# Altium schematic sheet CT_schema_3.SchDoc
size 339 x 183 mm
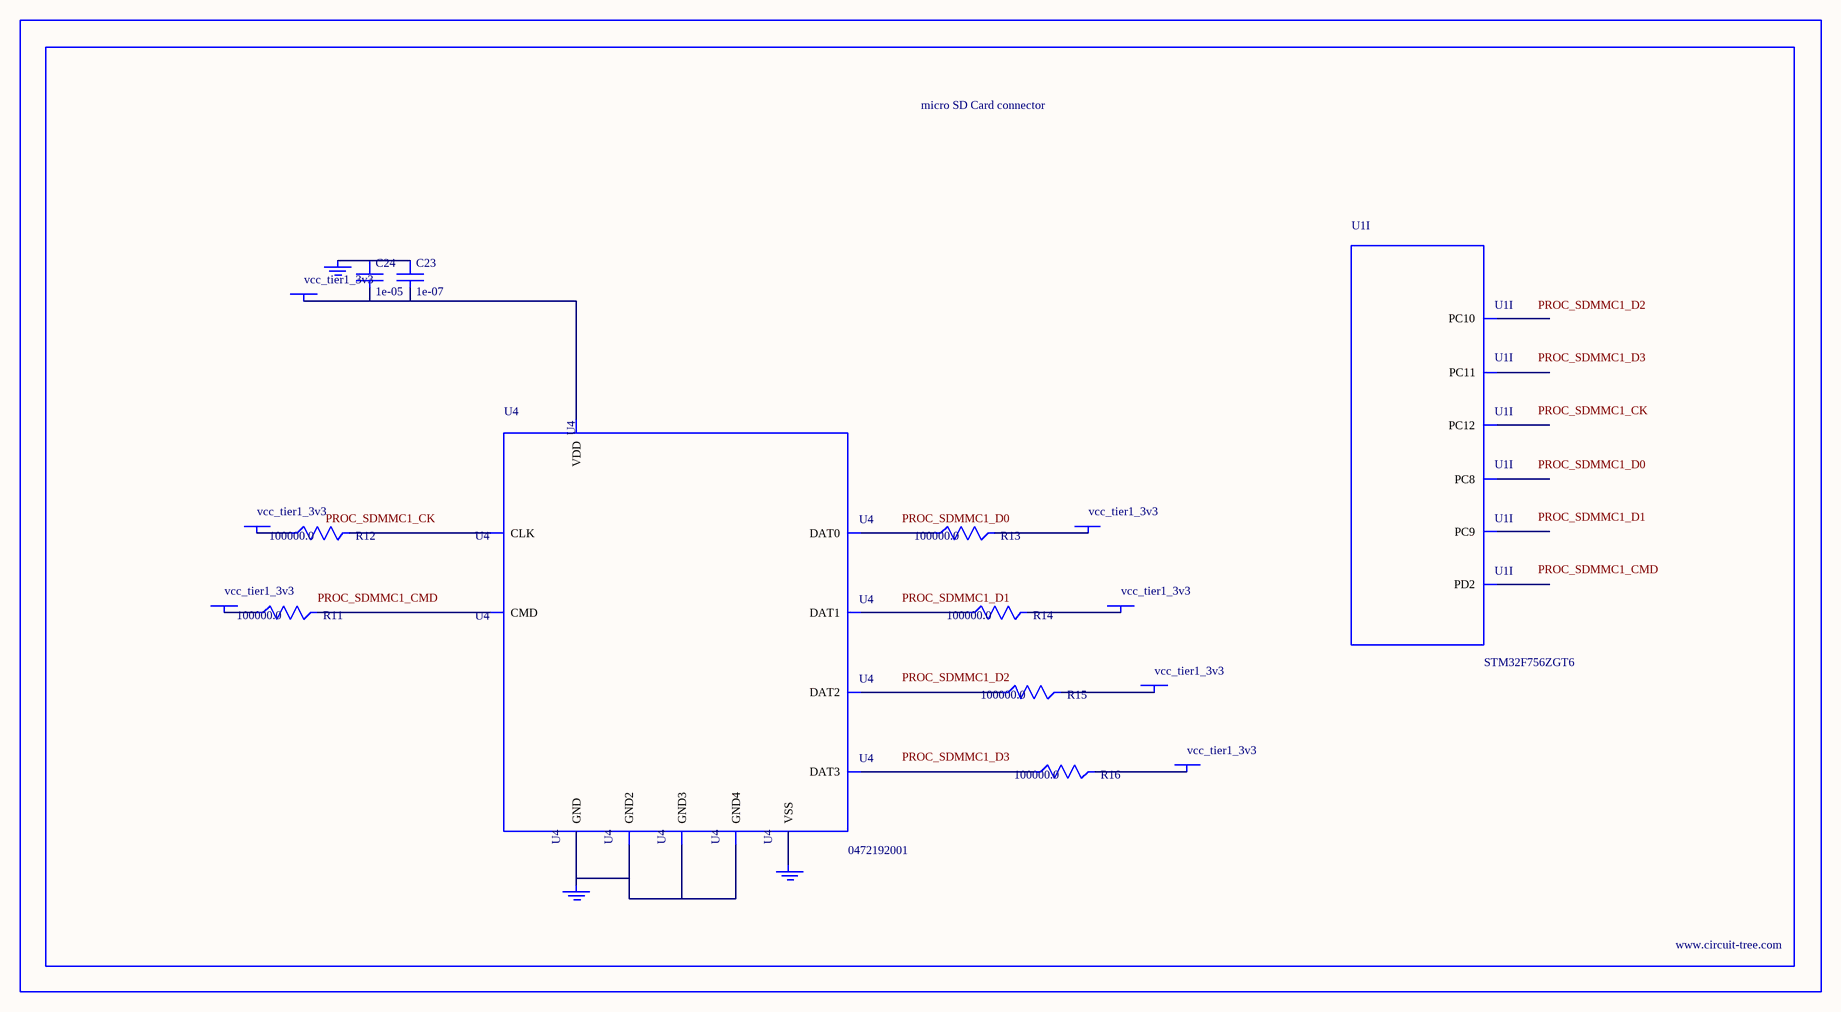
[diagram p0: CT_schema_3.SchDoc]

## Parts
BORDER2  (no value)
C23  1e-07  [C0402]
C24  1e-05  [C0805]
GND_INSTANCE_2_0  (no value)
GND_INSTANCE_2_1  (no value)
GND_INSTANCE_2_2  (no value)
POWER_INSTANCE_2_0  vcc_tier1_3v3
POWER_INSTANCE_2_1  vcc_tier1_3v3
POWER_INSTANCE_2_2  vcc_tier1_3v3
POWER_INSTANCE_2_3  vcc_tier1_3v3
POWER_INSTANCE_2_4  vcc_tier1_3v3
POWER_INSTANCE_2_5  vcc_tier1_3v3
POWER_INSTANCE_2_6  vcc_tier1_3v3
R11  100000.0  [R0603]
R12  100000.0  [R0603]
R13  100000.0  [R0603]
R14  100000.0  [R0603]
R15  100000.0  [R0603]
R16  100000.0  [R0603]
U1  STM32F756ZGT6  [LQFP144]  (part I of 11)
U4  0472192001  [MOLEX_47219-2001]

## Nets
NetC23_1: C23.1 C24.1 GND_INSTANCE_2_0.0(GND)
NetC23_2: C23.2 C24.2 POWER_INSTANCE_2_3.0(PWR) U4.4(VDD)
NetGND_INSTANCE_2_1_0: GND_INSTANCE_2_1.0(GND) U4.6(VSS)
NetGND_INSTANCE_2_2_0: GND_INSTANCE_2_2.0(GND) U4.G1(GND) U4.G2(GND2) U4.G3(GND3) U4.G4(GND4)
NetPOWER_INSTANCE_2_0_0: POWER_INSTANCE_2_0.0(PWR) R15.2
NetPOWER_INSTANCE_2_1_0: POWER_INSTANCE_2_1.0(PWR) R16.2
NetPOWER_INSTANCE_2_2_0: POWER_INSTANCE_2_2.0(PWR) R11.1
NetPOWER_INSTANCE_2_4_0: POWER_INSTANCE_2_4.0(PWR) R12.1
NetPOWER_INSTANCE_2_5_0: POWER_INSTANCE_2_5.0(PWR) R13.2
NetPOWER_INSTANCE_2_6_0: POWER_INSTANCE_2_6.0(PWR) R14.2
NetR11_2: R11.2 U4.3(CMD)
NetR12_2: R12.2 U4.5(CLK)
NetR13_1: R13.1 U4.7(DAT0)
NetR14_1: R14.1 U4.8(DAT1)
NetR15_1: R15.1 U4.1(DAT2)
NetR16_1: R16.1 U4.2(DAT3)

Not connected (* = marked no-connect by the designer): U1 98(PC8) 99(PC9) 111(PC10) 112(PC11) 113(PC12) 116(PD2)

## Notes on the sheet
- Labels drawn without touching a wire or pin: PROC_SDMMC1_CK, PROC_SDMMC1_CMD, PROC_SDMMC1_D0, PROC_SDMMC1_D1, PROC_SDMMC1_D2, PROC_SDMMC1_D3

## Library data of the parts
BORDER2 = BORDER_PAGE2
C23 = C0402C104K3RACTU
C24 = C0805C106K8RACTU
GND_INSTANCE_2_0-GND_INSTANCE_2_2 = GND
POWER_INSTANCE_2_0-POWER_INSTANCE_2_6 = PWR
R11-R16 = RC0603JR-07100KL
